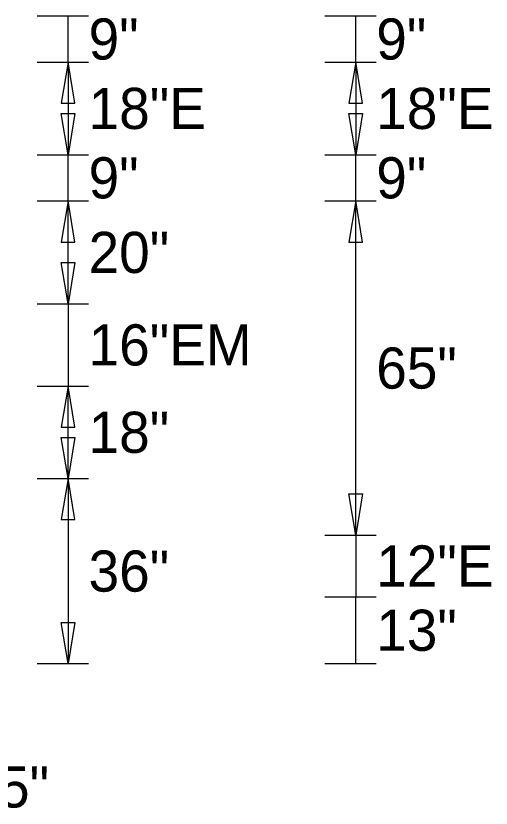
# Model space of a CAD drawing. Extents: x 2149961 to 2150220, y 145114 to 145240.
# Drawn here: x 2149988.25 to 2149995.96, y 145156.08 to 145168.92 of the extents above; entities that cross this region are included whole.
import ezdxf

# ---------------------------------------------------------------- set-up
doc = ezdxf.new("R2010")
doc.units = 0
doc.layers.add('GSDIMS', color=7, linetype='Continuous')

msp = doc.modelspace()

# ---------------------------------------------------------------- linework, layer by layer
at = {"layer": 'GSDIMS'}
for p, q in [((2149988.593, 145168.92), (2149989.426, 145168.92)), ((2149989.093, 145168.169), (2149989.093, 145168.92)), ((2149993.26, 145168.92), (2149994.093, 145168.92)), ((2149993.76, 145168.169), (2149993.76, 145168.92)), ((2149988.593, 145168.169), (2149989.426, 145168.169)), ((2149988.593, 145168.169), (2149989.426, 145168.169)), ((2149989.093, 145168.169), (2149989.093, 145166.669)), ((2149993.26, 145168.169), (2149994.093, 145168.169)), ((2149993.26, 145168.169), (2149994.093, 145168.169)), ((2149993.76, 145168.169), (2149993.76, 145166.669)), ((2149988.593, 145166.669), (2149989.426, 145166.669)), ((2149988.593, 145166.669), (2149989.426, 145166.669)), ((2149989.093, 145165.919), (2149989.093, 145166.669)), ((2149993.26, 145166.669), (2149994.093, 145166.669)), ((2149993.26, 145166.669), (2149994.093, 145166.669)), ((2149993.76, 145165.919), (2149993.76, 145166.669)), ((2149988.593, 145165.919), (2149989.426, 145165.919)), ((2149988.593, 145165.919), (2149989.426, 145165.919)), ((2149989.093, 145164.252), (2149989.093, 145165.919)), ((2149993.26, 145165.919), (2149994.093, 145165.919)), ((2149993.26, 145165.919), (2149994.093, 145165.919)), ((2149993.76, 145160.503), (2149993.76, 145165.919)), ((2149988.593, 145164.252), (2149989.426, 145164.252)), ((2149988.593, 145164.252), (2149989.426, 145164.252)), ((2149989.093, 145164.252), (2149989.093, 145162.919)), ((2149988.593, 145162.919), (2149989.426, 145162.919)), ((2149988.593, 145162.919), (2149989.426, 145162.919)), ((2149989.093, 145161.419), (2149989.093, 145162.919)), ((2149988.593, 145161.419), (2149989.426, 145161.419)), ((2149988.593, 145161.419), (2149989.426, 145161.419)), ((2149989.093, 145161.419), (2149989.093, 145158.419)), ((2149993.26, 145160.503), (2149994.093, 145160.503)), ((2149993.26, 145160.503), (2149994.093, 145160.503)), ((2149993.76, 145160.503), (2149993.76, 145159.503)), ((2149993.26, 145159.503), (2149994.093, 145159.503)), ((2149993.26, 145159.503), (2149994.093, 145159.503)), ((2149993.76, 145158.419), (2149993.76, 145159.503)), ((2149988.593, 145158.419), (2149989.426, 145158.419)), ((2149993.26, 145158.419), (2149994.093, 145158.419))]:
    msp.add_line(p, q, dxfattribs=at)
for points in [[(2149989.093, 145168.169), (2149988.982, 145167.503), (2149989.204, 145167.503)], [(2149993.76, 145168.169), (2149993.649, 145167.503), (2149993.871, 145167.503)], [(2149989.093, 145166.669), (2149988.982, 145167.336), (2149989.204, 145167.336)], [(2149993.76, 145166.669), (2149993.649, 145167.336), (2149993.871, 145167.336)], [(2149989.093, 145165.919), (2149988.982, 145165.252), (2149989.204, 145165.252)], [(2149993.76, 145165.919), (2149993.648, 145165.252), (2149993.871, 145165.252)], [(2149989.093, 145164.252), (2149988.982, 145164.919), (2149989.204, 145164.919)], [(2149989.093, 145162.919), (2149988.982, 145162.252), (2149989.204, 145162.252)], [(2149989.093, 145161.419), (2149988.982, 145162.086), (2149989.204, 145162.086)], [(2149989.093, 145161.419), (2149988.982, 145160.753), (2149989.204, 145160.753)], [(2149993.76, 145160.503), (2149993.648, 145161.169), (2149993.871, 145161.169)], [(2149989.093, 145158.419), (2149988.982, 145159.086), (2149989.204, 145159.086)]]:
    msp.add_lwpolyline(points, close=True, dxfattribs=at)

# ---------------------------------------------------------------- texts
for s, p in [('9"', (2149989.426, 145168.211)), ('9"', (2149994.093, 145168.211)), ('18"E', (2149989.426, 145167.086)), ('18"E', (2149994.093, 145167.086)), ('9"', (2149989.426, 145165.961)), ('9"', (2149994.093, 145165.961)), ('20"', (2149989.426, 145164.752)), ('16"EM', (2149989.426, 145163.252)), ('65"', (2149994.093, 145162.877)), ('18"', (2149989.426, 145161.836)), ('12"E', (2149994.093, 145159.669)), ('36"', (2149989.426, 145159.586)), ('13"', (2149994.093, 145158.627)), ('19.05"', (2149986.238, 145156.086))]:
    msp.add_text(s, height=0.6667, dxfattribs=at).set_placement(p)

doc.saveas('drawing.dxf')
